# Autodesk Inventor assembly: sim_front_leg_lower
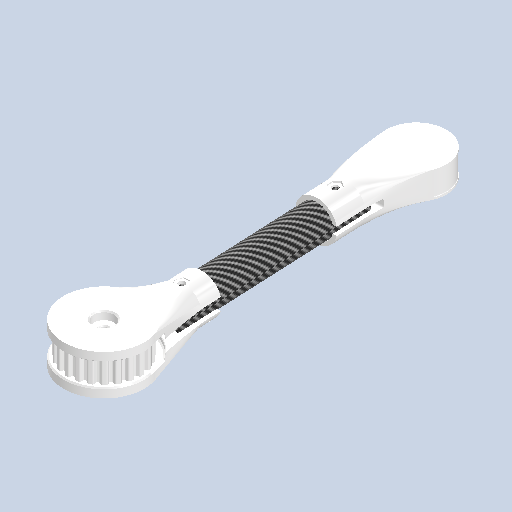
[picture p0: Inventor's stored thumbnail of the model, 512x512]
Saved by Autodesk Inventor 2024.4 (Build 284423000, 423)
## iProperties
Created: 2026-01
Part Number: sim_front_leg_lower
Document SubType Name: Assembly
Designer: AdminForWorker
Title: hind_leg_lower v2
Author: AdminForWorker
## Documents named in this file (4)
- c:\worker\convert-fusion-r06-cosv3\tmp\job-1\18\temp\files\f5f2e542-9eaa-411d-a97a-acdab94073cf\53f87cfb-3649-4959-9a8a-646742002cb6.iam
- c:\worker\convert-fusion-r06-cosv3\tmp\job-1\18\temp\files\f5f2e542-9eaa-411d-a97a-acdab94073cf\foot.ipt
- c:\worker\convert-fusion-r06-cosv3\tmp\job-1\18\temp\files\f5f2e542-9eaa-411d-a97a-acdab94073cf\knee.ipt
- c:\worker\convert-fusion-r06-cosv3\tmp\job-1\18\temp\files\f5f2e542-9eaa-411d-a97a-acdab94073cf\carbon_fiber_tube.ipt
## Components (3 placed, 3 different names)
1. foot:1
2. knee:1
3. carbon_fiber_tube:1
